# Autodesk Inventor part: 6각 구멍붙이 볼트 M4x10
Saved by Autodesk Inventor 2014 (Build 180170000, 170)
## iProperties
Created: 2025-10
Part Number: 6각 구멍붙이 볼트 M4x10
Material: 일반
Document SubType Name: Modeling
Designer: dg
Density: 1 g/cm^3
Appearance: 기본값
Author: dg
Author: jhkim
Description: 6각머리 태핑 나사
Creation Date: 2025-10-01
Sending System: Autodesk Inventor 2026
Preprocessor: ST-DEVELOPER v20.1
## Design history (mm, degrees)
node "6각 구멍붙이 볼트 M4x101"
body "Solid1"
node "기준1"
